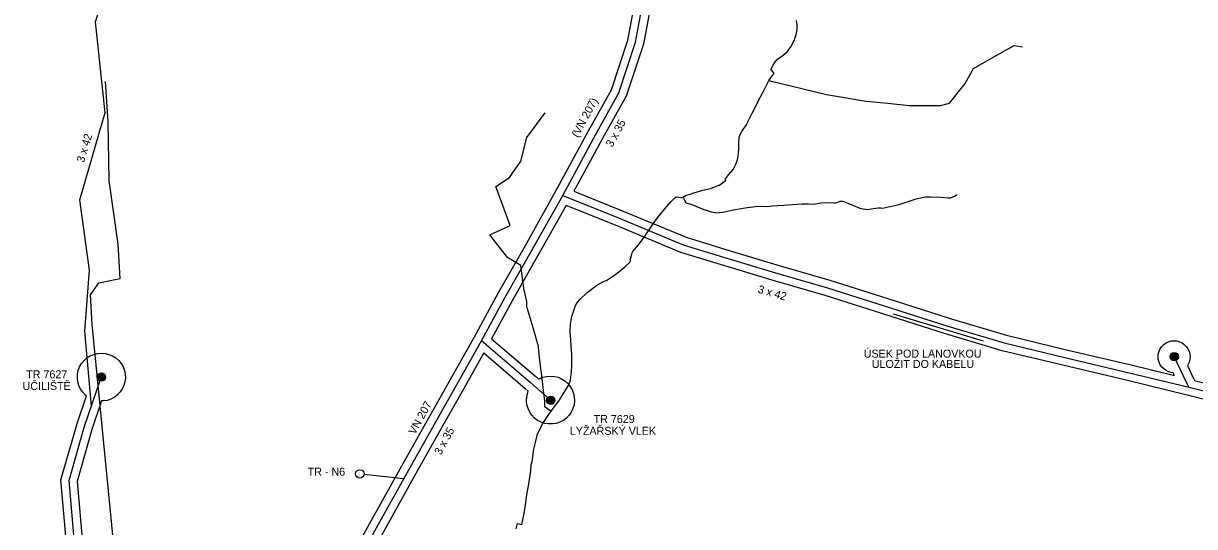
# Model space of a CAD drawing. Extents: x -439095 to -431527, y -1129525 to -1119219.
# Drawn here: x -438079 to -436616, y -1123382 to -1122754 of the extents above; entities that cross this region are included whole.
import ezdxf

# ---------------------------------------------------------------- set-up
doc = ezdxf.new("R2010")
doc.units = 0
for name, color, linetype in [('Hranice reseneho uzemi', 7, 'Continuous'), ('UZEMNI REZERVA', 7, 'Continuous'), ('Vrstva 11', 7, 'Continuous'), ('Vrstva 13', 7, 'Continuous'), ('Vrstva 19', 7, 'Continuous'), ('Vrstva 21', 7, 'Continuous'), ('ZU', 7, 'Continuous')]:
    doc.layers.add(name, color=color, linetype=linetype)

msp = doc.modelspace()

# ---------------------------------------------------------------- linework, layer by layer
at = {"layer": 'Hranice reseneho uzemi'}
msp.add_line((-437604.1, -1123323), (-437653.6, -1123317.3), dxfattribs=at)
for points in [[(-437994.2, -1123232.1), (-438002.3, -1123138.3), (-437996.7, -1123061.9), (-438008.7, -1122974.2), (-437977.1, -1122865), (-437977.1, -1122865.1), (-437989.1, -1122751.5), (-437967.6, -1122682.6), (-437917.7, -1122638.8), (-437924, -1122523.2), (-437915.1, -1122472.9)], [(-437670.6, -1123442.6), (-437636, -1123380.4), (-437597.6, -1123311.4), (-437564, -1123251.4), (-437538.1, -1123205.8), (-437506.9, -1123150.2), (-437477.3, -1123095.6), (-437443.3, -1123035.9), (-437405.4, -1122968.5), (-437364.4, -1122892.7), (-437335.2, -1122840.4), (-437314.3, -1122777), (-437305.5, -1122730.3)], [(-437405.4, -1122968.5), (-437335.8, -1122996.6), (-437254.7, -1123030.3), (-437204.4, -1123045.6), (-437204.4, -1123045.6), (-437136.7, -1123066.1), (-437074.5, -1123084.1), (-436993.2, -1123110), (-436924.2, -1123131.8), (-436853.7, -1123153), (-436778.2, -1123171.2), (-436699.3, -1123189.7), (-436622.9, -1123208.4), (-436534.9, -1123230.5)], [(-437506.8, -1123150), (-437445.7, -1123202.4), (-437420.6, -1123224.3)], [(-436623, -1123208.4), (-436629.6, -1123194.5), (-436641.4, -1123170)], [(-437977, -1123900.4), (-437982.6, -1123833.3), (-437982.6, -1123833.3), (-437987.7, -1123768.4), (-437994.8, -1123672.7), (-438001.8, -1123580), (-438008.5, -1123491), (-438015.4, -1123403.4), (-438022.1, -1123325), (-438003.1, -1123258.2), (-438003.1, -1123258.2), (-437981.9, -1123196)]]:
    msp.add_lwpolyline(points, dxfattribs=at)
at = {"layer": 'UZEMNI REZERVA'}
for points in [[(-437463.5, -1123385.1), (-437461.9, -1123378.8), (-437456.3, -1123379.9), (-437455.2, -1123374), (-437453.1, -1123363.5), (-437452.7, -1123361), (-437450.9, -1123349.5), (-437450.9, -1123348.8), (-437450.2, -1123342.9), (-437449.2, -1123338.1), (-437447.8, -1123329.5), (-437445.4, -1123312.2), (-437444.6, -1123305.4), (-437443.2, -1123299.5), (-437442.1, -1123290.8), (-437441.4, -1123285.7), (-437439, -1123275.9), (-437437.6, -1123270.4), (-437436.8, -1123266.5), (-437432.4, -1123257.8), (-437430.8, -1123254.2), (-437428.1, -1123250.4), (-437422.7, -1123242.3), (-437419.9, -1123238.4), (-437416, -1123233.1), (-437415.5, -1123232.5), (-437410.8, -1123226.2), (-437404.2, -1123216.3), (-437398.3, -1123206.2), (-437395.7, -1123198.9), (-437394.3, -1123188.9), (-437393.8, -1123181.7), (-437393.9, -1123174.3), (-437394.1, -1123166.8), (-437394.7, -1123157.7), (-437394.8, -1123157.1), (-437394.7, -1123156.8), (-437394.7, -1123156.4), (-437395.8, -1123142.6), (-437395.8, -1123142.3), (-437395.8, -1123142.3), (-437395.9, -1123142), (-437395.9, -1123141.9), (-437395.9, -1123141.7), (-437395.9, -1123137.8), (-437395.6, -1123129.6), (-437394.8, -1123124.3), (-437393.8, -1123119.8), (-437391.8, -1123113.7), (-437389.3, -1123106.1), (-437387.4, -1123102.9), (-437386.5, -1123101.7), (-437383.7, -1123098.2), (-437374.7, -1123089.9), (-437368.3, -1123084.7), (-437362.7, -1123080.8), (-437355.4, -1123076.4), (-437352.5, -1123075.5), (-437350.7, -1123075), (-437341.6, -1123068.8), (-437333.5, -1123062.6), (-437332.2, -1123061.6), (-437327.8, -1123057.8), (-437321.6, -1123051.8), (-437320.8, -1123050.5), (-437320.6, -1123048.7), (-437320.5, -1123048), (-437320.2, -1123046.7), (-437319.2, -1123042.1), (-437318.7, -1123040.3), (-437317.8, -1123038.5), (-437310.7, -1123030.2), (-437302.2, -1123018.9), (-437294.9, -1123007.8), (-437289.4, -1123000), (-437287.7, -1122997.7), (-437286.8, -1122996.4), (-437277.7, -1122985.2), (-437270.3, -1122976.4), (-437265, -1122971.3), (-437263.6, -1122970.5), (-437262.2, -1122970.5), (-437258.2, -1122971), (-437256.8, -1122971.3), (-437255.4, -1122970.9), (-437251, -1122968.3), (-437246.3, -1122966.8), (-437241.6, -1122965.2), (-437234.4, -1122963.2), (-437230.5, -1122962.1), (-437220.8, -1122959.8), (-437219.8, -1122959.3), (-437213.4, -1122956.8), (-437210.5, -1122955.9), (-437209.4, -1122955.7), (-437209.4, -1122955.7), (-437209.4, -1122955.7), (-437209.2, -1122955.6), (-437209.1, -1122955.6), (-437208.9, -1122955.4), (-437201.9, -1122949.8), (-437201.7, -1122949.7), (-437201.6, -1122949.6), (-437201.7, -1122949.4), (-437201.7, -1122949.3), (-437201.7, -1122949.3), (-437201.7, -1122949.3), (-437201.8, -1122948.9), (-437201.8, -1122947.8), (-437197.7, -1122942.5), (-437192.6, -1122936.3), (-437188.9, -1122929.3), (-437187.2, -1122924.1), (-437185.8, -1122916.4), (-437185.3, -1122910), (-437185.4, -1122902.7), (-437184.8, -1122896.6), (-437184.1, -1122893.3), (-437181.8, -1122888.5), (-437179, -1122884.9), (-437175.5, -1122879.7), (-437174.9, -1122878.4), (-437169, -1122866.5), (-437165, -1122858.5), (-437161, -1122850.6), (-437154.9, -1122838.9), (-437150.2, -1122829.7), (-437147.7, -1122824.9), (-437143.6, -1122819.2), (-437141.6, -1122816.6), (-437141.7, -1122815.4), (-437142.3, -1122814.4), (-437144.3, -1122812.5), (-437144.8, -1122811.8), (-437145.1, -1122810.3), (-437142.3, -1122805.9), (-437139.4, -1122801.3), (-437137.1, -1122798.3), (-437134.1, -1122796.1), (-437130, -1122793.2), (-437124.8, -1122788.9), (-437119.7, -1122781.4), (-437115.8, -1122773.7), (-437113.7, -1122767.3), (-437112.4, -1122761.5), (-437112.5, -1122755), (-437113.3, -1122749.7)], [(-437147.7, -1122824.9), (-437076, -1122842.3), (-437026.1, -1122850.6), (-436999.3, -1122853.4), (-436972.5, -1122856.2), (-436933.3, -1122856.2), (-436922, -1122853.1), (-436902.6, -1122828.8), (-436892.1, -1122809.7), (-436866.8, -1122795.4), (-436841.5, -1122781.1), (-436831, -1122783)], [(-437954.7, -1123524.9), (-437993.3, -1123129.4), (-437995.2, -1123092.7), (-437985.1, -1123077.6), (-437958.2, -1123072.2), (-437960.6, -1123029.4), (-437972, -1122949.8), (-437973.3, -1122876.6), (-437976.6, -1122826.2)], [(-437453.4, -1123087.8), (-437457.7, -1123056.1), (-437474.3, -1123046.2), (-437496.5, -1123017.8), (-437471.2, -1123006.1), (-437489.1, -1122957.4), (-437471.8, -1122946.3), (-437457.7, -1122925.9), (-437450.3, -1122896.3), (-437427.3, -1122865.1)], [(-437255.4, -1122970.9), (-437254.6, -1122971.9), (-437252.6, -1122975.3), (-437251.6, -1122977.2), (-437251.1, -1122977.8), (-437244.2, -1122979.8), (-437228.9, -1122986.2), (-437219.7, -1122989.2), (-437213, -1122990.1), (-437205.3, -1122989.4), (-437192.1, -1122986.7), (-437182.5, -1122984.9), (-437175, -1122983.5), (-437164.4, -1122982.3), (-437155.8, -1122982), (-437149.5, -1122982.4), (-437143.6, -1122981.6), (-437136.5, -1122981.2), (-437129.3, -1122980.6), (-437117.8, -1122979.8), (-437106.2, -1122979.2), (-437098.3, -1122979.2), (-437091.5, -1122979.4), (-437082.8, -1122978), (-437074.6, -1122977.5), (-437066.7, -1122977.7), (-437064.5, -1122977.6), (-437062.7, -1122977.3), (-437058.9, -1122975.9), (-437057.3, -1122975.6), (-437055.5, -1122975.9), (-437049.2, -1122978.1), (-437039.8, -1122982), (-437034.2, -1122984.3), (-437030.2, -1122985.5), (-437026.6, -1122985.9), (-437023.7, -1122986), (-437019.9, -1122985.5), (-437014, -1122984.5), (-437011.1, -1122984.1), (-437008, -1122984.1), (-437005.7, -1122984.5), (-436996.2, -1122982.4), (-436985.2, -1122979.8), (-436978.9, -1122977.9), (-436968.8, -1122974.3), (-436963.9, -1122972.7), (-436956.8, -1122971.2), (-436951.9, -1122970.4), (-436945.6, -1122970.3), (-436932.5, -1122970.9), (-436923.7, -1122971.6), (-436920.9, -1122971.6), (-436917.8, -1122970.4), (-436915.2, -1122969.2), (-436912.5, -1122967.4)], [(-437419.9, -1123238.4), (-437419.9, -1123238.4), (-437420.3, -1123238.1), (-437427.1, -1123233.3), (-437427.7, -1123232.6), (-437427.7, -1123232.2), (-437427.6, -1123231.5), (-437427.6, -1123231.4), (-437427.9, -1123225.2), (-437429.3, -1123212.3), (-437431, -1123197.5), (-437433.8, -1123175), (-437436.2, -1123154.6), (-437436.3, -1123154.4), (-437443.1, -1123131.1), (-437449.9, -1123109.2), (-437450.1, -1123107.4), (-437450.1, -1123101), (-437453.3, -1123088.4), (-437453.4, -1123087.8)]]:
    msp.add_lwpolyline(points, dxfattribs=at)
at = {"layer": 'Vrstva 11'}
for centre, radius in [((-436641.4, -1123170), 5.25), ((-436641.4, -1123170), 4.55), ((-436641.4, -1123170), 3.85), ((-436641.4, -1123170), 3.15), ((-436641.4, -1123170), 2.45), ((-436641.4, -1123170), 1.75), ((-436641.4, -1123170), 1.05), ((-436641.4, -1123170), 0.35), ((-437981.8, -1123195.6), 5.25), ((-437981.8, -1123195.6), 4.55), ((-437981.8, -1123195.6), 3.85), ((-437981.8, -1123195.6), 3.15), ((-437981.8, -1123195.6), 2.45), ((-437981.8, -1123195.6), 1.75), ((-437981.8, -1123195.6), 1.05), ((-437981.8, -1123195.6), 0.35), ((-437420.3, -1123224.7), 5.25), ((-437420.3, -1123224.7), 4.55), ((-437420.3, -1123224.7), 3.85), ((-437420.3, -1123224.7), 3.15), ((-437420.3, -1123224.7), 2.45), ((-437420.3, -1123224.7), 1.75), ((-437420.3, -1123224.7), 1.05), ((-437420.3, -1123224.7), 0.35)]:
    msp.add_circle(centre, radius, dxfattribs=at)
at = {"layer": 'Vrstva 13'}
msp.add_line((-436992.7, -1123116.7), (-436880, -1123150.2), dxfattribs=at)
at = {"layer": 'Vrstva 19'}
msp.add_circle((-437658.8, -1123316.7), 5.25, dxfattribs=at)
at = {"layer": 'ZU'}
for points in [[(-437283.2, -1122408.5), (-437281.3, -1122423.8), (-437273.5, -1122462.3), (-437264.9, -1122523.7), (-437254.8, -1122600.5), (-437283.5, -1122683.7), (-437295.7, -1122732.4), (-437304.6, -1122779.5), (-437326, -1122844.4), (-437355.6, -1122897.5), (-437391.3, -1122963.4)], [(-437943.7, -1123908), (-437926.8, -1123878.2), (-437926.8, -1123870.6), (-437922.5, -1123870.6), (-437903.2, -1123836.7), (-437867, -1123771.8), (-437831.4, -1123709.2), (-437793.9, -1123642.7), (-437752.5, -1123567.6), (-437730, -1123527.1), (-437679.3, -1123437.8), (-437644.8, -1123375.5), (-437606.3, -1123306.6), (-437572.7, -1123246.4), (-437546.8, -1123200.9), (-437515.7, -1123145.3), (-437486, -1123090.7), (-437452, -1123031), (-437414.2, -1122963.7), (-437373.1, -1122887.9), (-437344.4, -1122836.4), (-437324, -1122774.5), (-437315.3, -1122728.2)], [(-436616, -1123199.8), (-436532.6, -1123220.8), (-436445.5, -1123241.1), (-436379.7, -1123224), (-436309.9, -1123206.1), (-436242.7, -1123175.6), (-436176.4, -1123147.6), (-436105.4, -1123114.8), (-436041, -1123104.7), (-435970.4, -1123094.7), (-435914.8, -1123048.8), (-435854, -1122999.8), (-435852.2, -1122998.1), (-435807.7, -1122953.9), (-435793.4, -1122944.3)], [(-437391.3, -1122963.4), (-437332, -1122987.4), (-437251.3, -1123020.9), (-437201.6, -1123036), (-437133.9, -1123056.5), (-437071.6, -1123074.5), (-436990.2, -1123100.5), (-436921.3, -1123122.3), (-436851.1, -1123143.3), (-436775.9, -1123161.5), (-436696.9, -1123180), (-436641.1, -1123193.6)], [(-437401, -1122981.1), (-437434.6, -1123040.8), (-437468.5, -1123100.4), (-437494.2, -1123147.7)], [(-435841.1, -1123015.1), (-435902.2, -1123064.3), (-435962.1, -1123113.7), (-436038.1, -1123124.5), (-436099.5, -1123134.1), (-436168.3, -1123165.9), (-436234.7, -1123193.9), (-436303.2, -1123225), (-436374.7, -1123243.4), (-436445.2, -1123261.7), (-436537.3, -1123240.2), (-436625.3, -1123218.1), (-436701.6, -1123199.4), (-436780.5, -1123180.9), (-436856.3, -1123162.6), (-436927.2, -1123141.4), (-436996.2, -1123119.6), (-437077.4, -1123093.6), (-437139.6, -1123075.7), (-437207.2, -1123055.3), (-437207.2, -1123055.2), (-437258, -1123039.8), (-437339.6, -1123005.9), (-437401, -1122981.1)], [(-437494.2, -1123147.7), (-437439.1, -1123194.9), (-437435.3, -1123198.2)], [(-436642.8, -1123190.1), (-436645.1, -1123189.9), (-436648.5, -1123189), (-436651.6, -1123187.5), (-436654.5, -1123185.5), (-436657, -1123183.1), (-436659, -1123180.2), (-436660.4, -1123177.1), (-436661.3, -1123173.7), (-436661.6, -1123170.2), (-436661.3, -1123166.8), (-436660.4, -1123163.4), (-436659, -1123160.2), (-436657, -1123157.4), (-436654.5, -1123154.9), (-436651.6, -1123152.9), (-436648.5, -1123151.4), (-436645.1, -1123150.5)], [(-436645.1, -1123150.5), (-436641.6, -1123150.2), (-436638.2, -1123150.5), (-436634.8, -1123151.4), (-436631.6, -1123152.9), (-436628.8, -1123154.9), (-436626.3, -1123157.4), (-436624.3, -1123160.2), (-436622.9, -1123163.4), (-436621.9, -1123166.8), (-436621.6, -1123170.2), (-436621.9, -1123173.7), (-436622.9, -1123177.1), (-436624.3, -1123180.2), (-436624.9, -1123181.1)], [(-438000.3, -1123219.1), (-438001.7, -1123218.1), (-438005, -1123214.6), (-438007.8, -1123210.6), (-438009.8, -1123206.3), (-438011.2, -1123201.6), (-438011.7, -1123196.8), (-438011.6, -1123192), (-438010.6, -1123187.3), (-438008.9, -1123182.8), (-438006.5, -1123178.6), (-438003.4, -1123174.8), (-437999.8, -1123171.6), (-437995.7, -1123169.1), (-437991.3, -1123167.2), (-437986.6, -1123166), (-437981.8, -1123165.6), (-437977, -1123166), (-437972.3, -1123167.2), (-437967.8, -1123169.1), (-437963.7, -1123171.6), (-437960.1, -1123174.8), (-437957.1, -1123178.6), (-437954.7, -1123182.8), (-437953, -1123187.3), (-437952, -1123192), (-437951.8, -1123196.8), (-437952.4, -1123201.6), (-437953.7, -1123206.3), (-437955.8, -1123210.6), (-437958.5, -1123214.6), (-437961.9, -1123218.1), (-437965.7, -1123221), (-437970, -1123223.2), (-437974.6, -1123224.7), (-437979.4, -1123225.5), (-437981.4, -1123225.5)], [(-437504.1, -1123165.5), (-437529.4, -1123210.7), (-437555.3, -1123256.3), (-437588.9, -1123316.3), (-437627.3, -1123385.3), (-437661.9, -1123447.5), (-437710.8, -1123533.8)], [(-437504.1, -1123165.5), (-437452.2, -1123210), (-437448.4, -1123213.3)], [(-436624.9, -1123181.1), (-436620.6, -1123190.2), (-436616, -1123199.8)], [(-437435.3, -1123198.2), (-437434.6, -1123197.8), (-437430.1, -1123195.9), (-437425.5, -1123194.7), (-437420.6, -1123194.3), (-437415.8, -1123194.7), (-437411.1, -1123195.9), (-437406.7, -1123197.8), (-437402.6, -1123200.3), (-437399, -1123203.5), (-437396, -1123207.3), (-437393.5, -1123211.5), (-437391.8, -1123216), (-437390.9, -1123220.7), (-437390.7, -1123225.5), (-437391.2, -1123230.3), (-437392.6, -1123235), (-437394.7, -1123239.3), (-437397.4, -1123243.3), (-437400.7, -1123246.8), (-437404.6, -1123249.7), (-437408.9, -1123251.9), (-437413.5, -1123253.5), (-437418.2, -1123254.2), (-437423.1, -1123254.2), (-437427.8, -1123253.5), (-437432.4, -1123251.9), (-437436.7, -1123249.7), (-437440.5, -1123246.8), (-437443.9, -1123243.3), (-437446.6, -1123239.3), (-437448.7, -1123235), (-437450, -1123230.3), (-437450.6, -1123225.5), (-437450.4, -1123220.7), (-437449.5, -1123216), (-437448.4, -1123213.3)], [(-436641.1, -1123193.6), (-436642.8, -1123190.1)], [(-437988.1, -1123887.5), (-437992.6, -1123833.7), (-437992.6, -1123833.7), (-437997.7, -1123769.2), (-438004.7, -1123673.4), (-438011.8, -1123580.7), (-438018.5, -1123491.8), (-438025.4, -1123404.2), (-438032.2, -1123324), (-438012.6, -1123255.3), (-438012.5, -1123255), (-438000.3, -1123219.1)], [(-437981.4, -1123225.5), (-437993.5, -1123261.2), (-438012, -1123326), (-438005.4, -1123402.5), (-437998.5, -1123490.2), (-437991.8, -1123579.2), (-437984.8, -1123671.9), (-437977.8, -1123767.7), (-437972.7, -1123832.6), (-437967.1, -1123899.6)]]:
    msp.add_lwpolyline(points, dxfattribs=at)

# ---------------------------------------------------------------- texts
at = {"layer": 'Vrstva 13'}
for s, rotation, p in [('(VN 207)', 61.6991, (-437386.3, -1122897)), ('3 x 35', 61.2474, (-437343.6, -1122909)), ('3 x 42', 73.2854, (-438003.5, -1122928.1)), ('3 x 42', 343.6959, (-437162.4, -1123089.9)), ('VN 207', 61.2472, (-437590, -1123268.4)), ('3 x 35', 61.2473, (-437557.7, -1123293.8))]:
    msp.add_text(s, height=10, rotation=rotation, dxfattribs=at).set_placement(p)
for s, p in [('ÚSEK POD LANOVKOU', (-437029.3, -1123171.3)), ('ULOŽIT DO KABELU', (-437019.2, -1123184.2)), ('TR 7627', (-438075.6, -1123197.2)), ('UČILIŠTĚ', (-438080.2, -1123211.8)), ('TR 7629', (-437366.7, -1123253)), ('LYŽAŘSKÝ VLEK', (-437396.5, -1123267.8))]:
    msp.add_text(s, height=10, dxfattribs=at).set_placement(p)
at = {"layer": 'Vrstva 21'}
msp.add_text('TR - N6', height=10, dxfattribs=at).set_placement((-437724, -1123318.9))

doc.saveas('drawing.dxf')
